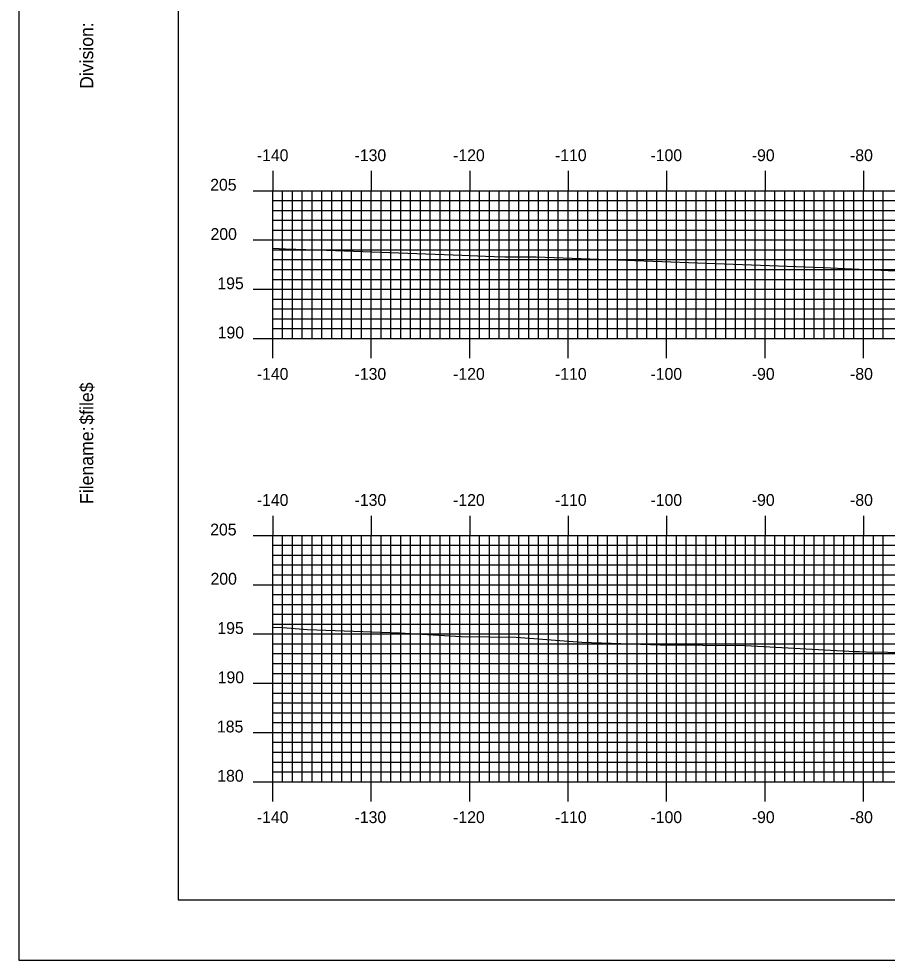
# Model space of a CAD drawing. Extents: x 851300 to 851643, y 366898 to 367118.
# Drawn here: x 851299.7 to 851387.9, y 366898.4 to 366993.9 of the extents above; entities that cross this region are included whole.
import ezdxf

# ---------------------------------------------------------------- set-up
doc = ezdxf.new("R2010")
doc.units = 0
for name, color, linetype in [('BORDER', 7, 'Continuous'), ('H_V ANNOTATION', 7, 'Continuous'), ('MAJOR', 7, 'Continuous'), ('MINOR', 7, 'Continuous'), ('PLOT BOUNDARY', 7, 'Continuous'), ('S_Roadway_Centerline', 7, 'Continuous')]:
    doc.layers.add(name, color=color, linetype=linetype)

msp = doc.modelspace()

# ---------------------------------------------------------------- linework, layer by layer
at = {"layer": 'BORDER'}
msp.add_lwpolyline([(851315.905, 366904.473), (851635.905, 366904.473), (851635.905, 367114.473), (851315.905, 367114.473)], close=True, dxfattribs=at)
at = {"layer": 'MAJOR'}
for p, q in [((851325.505, 366978.477), (851325.505, 366976.473)), ((851335.505, 366978.477), (851335.505, 366976.473)), ((851345.505, 366978.477), (851345.505, 366976.473)), ((851355.505, 366978.477), (851355.505, 366976.473)), ((851365.505, 366978.477), (851365.505, 366976.473)), ((851375.505, 366978.477), (851375.505, 366976.473)), ((851385.505, 366978.477), (851385.505, 366976.473)), ((851323.501, 366976.473), (851325.505, 366976.473)), ((851325.505, 366976.473), (851465.505, 366976.473)), ((851325.505, 366961.473), (851325.505, 366976.473)), ((851325.505, 366961.473), (851325.505, 366976.473)), ((851325.505, 366976.473), (851465.505, 366976.473)), ((851335.505, 366961.473), (851335.505, 366976.473)), ((851345.505, 366961.473), (851345.505, 366976.473)), ((851355.505, 366961.473), (851355.505, 366976.473)), ((851365.505, 366961.473), (851365.505, 366976.473)), ((851375.505, 366961.473), (851375.505, 366976.473)), ((851385.505, 366961.473), (851385.505, 366976.473)), ((851323.501, 366971.473), (851325.505, 366971.473)), ((851325.505, 366971.473), (851465.505, 366971.473)), ((851323.501, 366966.473), (851325.505, 366966.473)), ((851325.505, 366966.473), (851465.505, 366966.473)), ((851323.501, 366961.473), (851325.505, 366961.473)), ((851325.505, 366961.473), (851465.505, 366961.473)), ((851325.505, 366961.473), (851465.505, 366961.473)), ((851325.505, 366959.469), (851325.505, 366961.473)), ((851335.505, 366959.469), (851335.505, 366961.473)), ((851345.505, 366959.469), (851345.505, 366961.473)), ((851355.505, 366959.469), (851355.505, 366961.473)), ((851365.505, 366959.469), (851365.505, 366961.473)), ((851375.505, 366959.469), (851375.505, 366961.473)), ((851385.505, 366959.469), (851385.505, 366961.473)), ((851325.505, 366943.477), (851325.505, 366941.473)), ((851335.505, 366943.477), (851335.505, 366941.473)), ((851345.505, 366943.477), (851345.505, 366941.473)), ((851355.505, 366943.477), (851355.505, 366941.473)), ((851365.505, 366943.477), (851365.505, 366941.473)), ((851375.505, 366943.477), (851375.505, 366941.473)), ((851385.505, 366943.477), (851385.505, 366941.473)), ((851323.501, 366941.473), (851325.505, 366941.473)), ((851325.505, 366941.473), (851605.505, 366941.473)), ((851325.505, 366916.473), (851325.505, 366941.473)), ((851325.505, 366916.473), (851325.505, 366941.473)), ((851325.505, 366941.473), (851605.505, 366941.473)), ((851335.505, 366916.473), (851335.505, 366941.473)), ((851345.505, 366916.473), (851345.505, 366941.473)), ((851355.505, 366916.473), (851355.505, 366941.473)), ((851365.505, 366916.473), (851365.505, 366941.473)), ((851375.505, 366916.473), (851375.505, 366941.473)), ((851385.505, 366916.473), (851385.505, 366941.473)), ((851323.501, 366936.473), (851325.505, 366936.473)), ((851325.505, 366936.473), (851605.505, 366936.473)), ((851323.501, 366931.473), (851325.505, 366931.473)), ((851325.505, 366931.473), (851605.505, 366931.473)), ((851323.501, 366926.473), (851325.505, 366926.473)), ((851325.505, 366926.473), (851605.505, 366926.473)), ((851323.501, 366921.473), (851325.505, 366921.473)), ((851325.505, 366921.473), (851605.505, 366921.473)), ((851323.501, 366916.473), (851325.505, 366916.473)), ((851325.505, 366916.473), (851605.505, 366916.473)), ((851325.505, 366916.473), (851605.505, 366916.473)), ((851325.505, 366914.469), (851325.505, 366916.473)), ((851335.505, 366914.469), (851335.505, 366916.473)), ((851345.505, 366914.469), (851345.505, 366916.473)), ((851355.505, 366914.469), (851355.505, 366916.473)), ((851365.505, 366914.469), (851365.505, 366916.473)), ((851375.505, 366914.469), (851375.505, 366916.473)), ((851385.505, 366914.469), (851385.505, 366916.473))]:
    msp.add_line(p, q, dxfattribs=at)
at = {"layer": 'MINOR'}
for p, q in [((851325.505, 366961.473), (851325.505, 366976.473)), ((851326.505, 366961.473), (851326.505, 366976.473)), ((851327.505, 366961.473), (851327.505, 366976.473)), ((851328.505, 366961.473), (851328.505, 366976.473)), ((851329.505, 366961.473), (851329.505, 366976.473)), ((851330.505, 366961.473), (851330.505, 366976.473)), ((851331.505, 366961.473), (851331.505, 366976.473)), ((851332.505, 366961.473), (851332.505, 366976.473)), ((851333.505, 366961.473), (851333.505, 366976.473)), ((851334.505, 366961.473), (851334.505, 366976.473)), ((851336.505, 366961.473), (851336.505, 366976.473)), ((851337.505, 366961.473), (851337.505, 366976.473)), ((851338.505, 366961.473), (851338.505, 366976.473)), ((851339.505, 366961.473), (851339.505, 366976.473)), ((851340.505, 366961.473), (851340.505, 366976.473)), ((851341.505, 366961.473), (851341.505, 366976.473)), ((851342.505, 366961.473), (851342.505, 366976.473)), ((851343.505, 366961.473), (851343.505, 366976.473)), ((851344.505, 366961.473), (851344.505, 366976.473)), ((851346.505, 366961.473), (851346.505, 366976.473)), ((851347.505, 366961.473), (851347.505, 366976.473)), ((851348.505, 366961.473), (851348.505, 366976.473)), ((851349.505, 366961.473), (851349.505, 366976.473)), ((851350.505, 366961.473), (851350.505, 366976.473)), ((851351.505, 366961.473), (851351.505, 366976.473)), ((851352.505, 366961.473), (851352.505, 366976.473)), ((851353.505, 366961.473), (851353.505, 366976.473)), ((851354.505, 366961.473), (851354.505, 366976.473)), ((851356.505, 366961.473), (851356.505, 366976.473)), ((851357.505, 366961.473), (851357.505, 366976.473)), ((851358.505, 366961.473), (851358.505, 366976.473)), ((851359.505, 366961.473), (851359.505, 366976.473)), ((851360.505, 366961.473), (851360.505, 366976.473)), ((851361.505, 366961.473), (851361.505, 366976.473)), ((851362.505, 366961.473), (851362.505, 366976.473)), ((851363.505, 366961.473), (851363.505, 366976.473)), ((851364.505, 366961.473), (851364.505, 366976.473)), ((851366.505, 366961.473), (851366.505, 366976.473)), ((851367.505, 366961.473), (851367.505, 366976.473)), ((851368.505, 366961.473), (851368.505, 366976.473)), ((851369.505, 366961.473), (851369.505, 366976.473)), ((851370.505, 366961.473), (851370.505, 366976.473)), ((851371.505, 366961.473), (851371.505, 366976.473)), ((851372.505, 366961.473), (851372.505, 366976.473)), ((851373.505, 366961.473), (851373.505, 366976.473)), ((851374.505, 366961.473), (851374.505, 366976.473)), ((851376.505, 366961.473), (851376.505, 366976.473)), ((851377.505, 366961.473), (851377.505, 366976.473)), ((851378.505, 366961.473), (851378.505, 366976.473)), ((851379.505, 366961.473), (851379.505, 366976.473)), ((851380.505, 366961.473), (851380.505, 366976.473)), ((851381.505, 366961.473), (851381.505, 366976.473)), ((851382.505, 366961.473), (851382.505, 366976.473)), ((851383.505, 366961.473), (851383.505, 366976.473)), ((851384.505, 366961.473), (851384.505, 366976.473)), ((851386.505, 366961.473), (851386.505, 366976.473)), ((851387.505, 366961.473), (851387.505, 366976.473)), ((851325.505, 366975.473), (851465.505, 366975.473)), ((851325.505, 366975.473), (851327.509, 366975.473)), ((851325.505, 366974.473), (851465.505, 366974.473)), ((851325.505, 366974.473), (851327.509, 366974.473)), ((851325.505, 366973.473), (851465.505, 366973.473)), ((851325.505, 366973.473), (851327.509, 366973.473)), ((851325.505, 366972.473), (851465.505, 366972.473)), ((851325.505, 366972.473), (851327.509, 366972.473)), ((851325.505, 366970.473), (851465.505, 366970.473)), ((851325.505, 366970.473), (851327.509, 366970.473)), ((851325.505, 366969.473), (851465.505, 366969.473)), ((851325.505, 366969.473), (851327.509, 366969.473)), ((851325.505, 366968.473), (851465.505, 366968.473)), ((851325.505, 366968.473), (851327.509, 366968.473)), ((851325.505, 366967.473), (851465.505, 366967.473)), ((851325.505, 366967.473), (851327.509, 366967.473)), ((851325.505, 366965.473), (851465.505, 366965.473)), ((851325.505, 366965.473), (851327.509, 366965.473)), ((851325.505, 366964.473), (851465.505, 366964.473)), ((851325.505, 366964.473), (851327.509, 366964.473)), ((851325.505, 366963.473), (851465.505, 366963.473)), ((851325.505, 366963.473), (851327.509, 366963.473)), ((851325.505, 366962.473), (851465.505, 366962.473)), ((851325.505, 366962.473), (851327.509, 366962.473)), ((851326.505, 366916.473), (851326.505, 366941.473)), ((851327.505, 366916.473), (851327.505, 366941.473)), ((851328.505, 366916.473), (851328.505, 366941.473)), ((851329.505, 366916.473), (851329.505, 366941.473)), ((851330.505, 366916.473), (851330.505, 366941.473)), ((851331.505, 366916.473), (851331.505, 366941.473)), ((851332.505, 366916.473), (851332.505, 366941.473)), ((851333.505, 366916.473), (851333.505, 366941.473)), ((851334.505, 366916.473), (851334.505, 366941.473)), ((851336.505, 366916.473), (851336.505, 366941.473)), ((851337.505, 366916.473), (851337.505, 366941.473)), ((851338.505, 366916.473), (851338.505, 366941.473)), ((851339.505, 366916.473), (851339.505, 366941.473)), ((851340.505, 366916.473), (851340.505, 366941.473)), ((851341.505, 366916.473), (851341.505, 366941.473)), ((851342.505, 366916.473), (851342.505, 366941.473)), ((851343.505, 366916.473), (851343.505, 366941.473)), ((851344.505, 366916.473), (851344.505, 366941.473)), ((851346.505, 366916.473), (851346.505, 366941.473)), ((851347.505, 366916.473), (851347.505, 366941.473)), ((851348.505, 366916.473), (851348.505, 366941.473)), ((851349.505, 366916.473), (851349.505, 366941.473)), ((851350.505, 366916.473), (851350.505, 366941.473)), ((851351.505, 366916.473), (851351.505, 366941.473)), ((851352.505, 366916.473), (851352.505, 366941.473)), ((851353.505, 366916.473), (851353.505, 366941.473)), ((851354.505, 366916.473), (851354.505, 366941.473)), ((851356.505, 366916.473), (851356.505, 366941.473)), ((851357.505, 366916.473), (851357.505, 366941.473)), ((851358.505, 366916.473), (851358.505, 366941.473)), ((851359.505, 366916.473), (851359.505, 366941.473)), ((851360.505, 366916.473), (851360.505, 366941.473)), ((851361.505, 366916.473), (851361.505, 366941.473)), ((851362.505, 366916.473), (851362.505, 366941.473)), ((851363.505, 366916.473), (851363.505, 366941.473)), ((851364.505, 366916.473), (851364.505, 366941.473)), ((851366.505, 366916.473), (851366.505, 366941.473)), ((851367.505, 366916.473), (851367.505, 366941.473)), ((851368.505, 366916.473), (851368.505, 366941.473)), ((851369.505, 366916.473), (851369.505, 366941.473)), ((851370.505, 366916.473), (851370.505, 366941.473)), ((851371.505, 366916.473), (851371.505, 366941.473)), ((851372.505, 366916.473), (851372.505, 366941.473)), ((851373.505, 366916.473), (851373.505, 366941.473)), ((851374.505, 366916.473), (851374.505, 366941.473)), ((851376.505, 366916.473), (851376.505, 366941.473)), ((851377.505, 366916.473), (851377.505, 366941.473)), ((851378.505, 366916.473), (851378.505, 366941.473)), ((851379.505, 366916.473), (851379.505, 366941.473)), ((851380.505, 366916.473), (851380.505, 366941.473)), ((851381.505, 366916.473), (851381.505, 366941.473)), ((851382.505, 366916.473), (851382.505, 366941.473)), ((851383.505, 366916.473), (851383.505, 366941.473)), ((851384.505, 366916.473), (851384.505, 366941.473)), ((851386.505, 366916.473), (851386.505, 366941.473)), ((851387.505, 366916.473), (851387.505, 366941.473)), ((851325.505, 366940.473), (851605.505, 366940.473)), ((851325.505, 366940.473), (851327.509, 366940.473)), ((851325.505, 366939.473), (851605.505, 366939.473)), ((851325.505, 366939.473), (851327.509, 366939.473)), ((851325.505, 366938.473), (851605.505, 366938.473)), ((851325.505, 366938.473), (851327.509, 366938.473)), ((851325.505, 366937.473), (851605.505, 366937.473)), ((851325.505, 366937.473), (851327.509, 366937.473)), ((851325.505, 366935.473), (851605.505, 366935.473)), ((851325.505, 366935.473), (851327.509, 366935.473)), ((851325.505, 366934.473), (851605.505, 366934.473)), ((851325.505, 366934.473), (851327.509, 366934.473)), ((851325.505, 366933.473), (851605.505, 366933.473)), ((851325.505, 366933.473), (851327.509, 366933.473)), ((851325.505, 366932.473), (851605.505, 366932.473)), ((851325.505, 366932.473), (851327.509, 366932.473)), ((851325.505, 366930.473), (851605.505, 366930.473)), ((851325.505, 366930.473), (851327.509, 366930.473)), ((851325.505, 366929.473), (851605.505, 366929.473)), ((851325.505, 366929.473), (851327.509, 366929.473)), ((851325.505, 366928.473), (851605.505, 366928.473)), ((851325.505, 366928.473), (851327.509, 366928.473)), ((851325.505, 366927.473), (851605.505, 366927.473)), ((851325.505, 366927.473), (851327.509, 366927.473)), ((851325.505, 366925.473), (851605.505, 366925.473)), ((851325.505, 366925.473), (851327.509, 366925.473)), ((851325.505, 366924.473), (851605.505, 366924.473)), ((851325.505, 366924.473), (851327.509, 366924.473)), ((851325.505, 366923.473), (851605.505, 366923.473)), ((851325.505, 366923.473), (851327.509, 366923.473)), ((851325.505, 366922.473), (851605.505, 366922.473)), ((851325.505, 366922.473), (851327.509, 366922.473)), ((851325.505, 366920.473), (851605.505, 366920.473)), ((851325.505, 366920.473), (851327.509, 366920.473)), ((851325.505, 366919.473), (851605.505, 366919.473)), ((851325.505, 366919.473), (851327.509, 366919.473)), ((851325.505, 366918.473), (851605.505, 366918.473)), ((851325.505, 366918.473), (851327.509, 366918.473)), ((851325.505, 366917.473), (851605.505, 366917.473)), ((851325.505, 366917.473), (851327.509, 366917.473))]:
    msp.add_line(p, q, dxfattribs=at)
at = {"layer": 'PLOT BOUNDARY'}
msp.add_lwpolyline([(851299.718, 366898.355), (851639.718, 366898.355), (851639.718, 367118.355), (851299.718, 367118.355)], close=True, dxfattribs=at)
at = {"layer": 'S_Roadway_Centerline'}
for points in [[(851325.505, 366970.628), (851326.789, 366970.563), (851330.95, 366970.44), (851344.728, 366969.94), (851347.119, 366969.841), (851347.984, 366969.798), (851349.083, 366969.773), (851352.264, 366969.764), (851381.416, 366968.689), (851393.151, 366968.15)], [(851325.505, 366932.152), (851326.526, 366932.127), (851329.052, 366931.922), (851338.382, 366931.602), (851344.65, 366931.214), (851350.228, 366931.148), (851356.88, 366930.64), (851364.857, 366930.375), (851373.528, 366930.314), (851384.635, 366929.703), (851385.109, 366929.707), (851385.776, 366929.649), (851396.751, 366929.49)]]:
    msp.add_lwpolyline(points, dxfattribs=at)

# ---------------------------------------------------------------- texts
at = {"layer": 'BORDER'}
for s, p in [('Division:', (851307.275, 366986.805)), ('$file$', (851307.275, 366952.724)), ('Filename:', (851307.275, 366944.67))]:
    msp.add_text(s, height=1.3392, rotation=90, dxfattribs=at).set_placement(p)
at = {"layer": 'H_V ANNOTATION'}
for s, p in [('-140', (851323.889, 366979.473)), ('-130', (851333.814, 366979.473)), ('-120', (851343.824, 366979.473)), ('-110', (851354.167, 366979.473)), ('-100', (851363.867, 366979.473)), ('-90', (851374.156, 366979.473)), ('-80', (851384.135, 366979.473)), ('205', (851319.154, 366976.473)), ('200', (851319.186, 366971.473)), ('195', (851319.883, 366966.473)), ('190', (851319.915, 366961.473)), ('-140', (851323.889, 366957.273)), ('-130', (851333.814, 366957.273)), ('-120', (851343.824, 366957.273)), ('-110', (851354.167, 366957.273)), ('-100', (851363.867, 366957.273)), ('-90', (851374.156, 366957.273)), ('-80', (851384.135, 366957.273)), ('-140', (851323.889, 366944.473)), ('-130', (851333.814, 366944.473)), ('-120', (851343.824, 366944.473)), ('-110', (851354.167, 366944.473)), ('-100', (851363.867, 366944.473)), ('-90', (851374.156, 366944.473)), ('-80', (851384.135, 366944.473)), ('205', (851319.154, 366941.473)), ('200', (851319.186, 366936.473)), ('195', (851319.883, 366931.473)), ('190', (851319.915, 366926.473)), ('185', (851319.84, 366921.473)), ('180', (851319.872, 366916.473)), ('-140', (851323.889, 366912.273)), ('-130', (851333.814, 366912.273)), ('-120', (851343.824, 366912.273)), ('-110', (851354.167, 366912.273)), ('-100', (851363.867, 366912.273)), ('-90', (851374.156, 366912.273)), ('-80', (851384.135, 366912.273))]:
    msp.add_text(s, height=1.2, dxfattribs=at).set_placement(p)
at = {"layer": 'MAJOR'}
for p in [(851325.496, 366961.473), (851325.496, 366916.473)]:
    msp.add_text('-', height=0.012, dxfattribs=at).set_placement(p)

doc.saveas('drawing.dxf')
